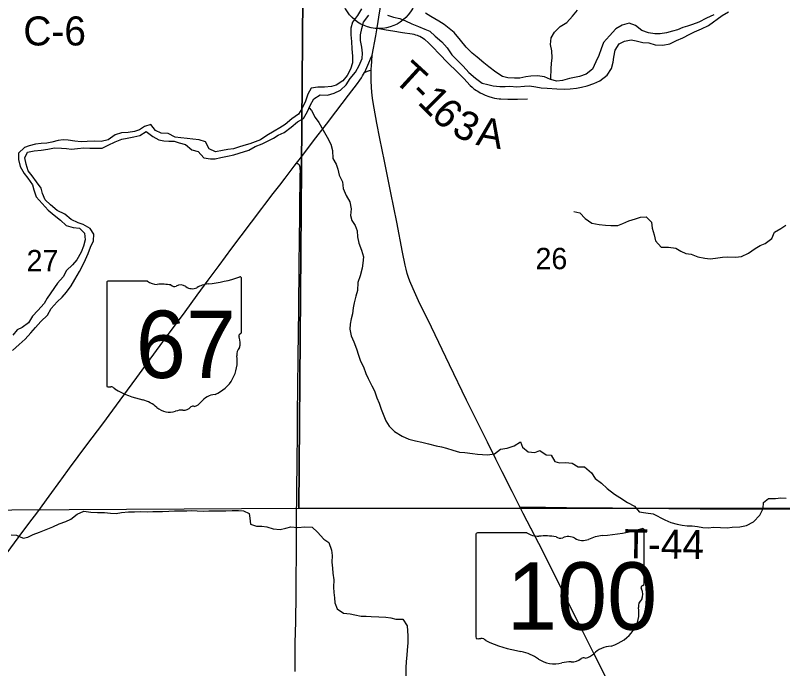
# Model space of a CAD drawing. Extents: x 0 to 34, y 0 to 22.
# Drawn here: x 7.184 to 7.934, y 14.745 to 15.384 of the extents above; entities that cross this region are included whole.
import ezdxf

# ---------------------------------------------------------------- set-up
doc = ezdxf.new("R2010")
doc.units = 0
for name, color, linetype in [('Default', 7, 'Continuous'), ('GM_X_County_Road_Text', 7, 'Continuous'), ('GM_X_Interchange_Ramps', 7, 'Continuous'), ('GM_X_Major_River', 7, 'Continuous'), ('GM_X_Minor_River', 7, 'Continuous'), ('GM_X_Section', 7, 'Continuous'), ('GM_X_Section_Text', 7, 'Continuous'), ('GM_X_State_Location', 7, 'Continuous'), ('GM_X_State_Route', 7, 'Continuous'), ('GM_X_State_Shield', 7, 'Continuous'), ('GM_X_Township_Road', 7, 'Continuous'), ('GM_X_Township_Road_Text', 7, 'Continuous'), ('GM_X_Unincorporated', 7, 'Continuous')]:
    doc.layers.add(name, color=color, linetype=linetype)

msp = doc.modelspace()

# ---------------------------------------------------------------- linework, layer by layer
at = {"layer": 'Default'}
msp.add_line((7.92809, 14.4004), (7.74937, 14.75957), dxfattribs=at)
msp.add_lwpolyline([(7.69144, 14.87495), (7.68009, 14.89684), (7.66922, 14.91837), (7.65961, 14.93739), (7.65347, 14.94996), (7.64531, 14.96644), (7.62464, 15.00761), (7.60807, 15.04207), (7.59039, 15.07893), (7.57789, 15.10487), (7.57257, 15.11647), (7.56943, 15.12394), (7.56809, 15.12753), (7.56675, 15.13163), (7.5656, 15.1359), (7.56475, 15.13978), (7.56219, 15.15228), (7.55651, 15.18158), (7.55066, 15.21052), (7.54457, 15.24131), (7.54011, 15.26356), (7.53717, 15.27851), (7.53444, 15.29318), (7.5332, 15.30086), (7.53257, 15.3058), (7.53188, 15.31325), (7.53147, 15.32072), (7.53139, 15.32726), (7.53146, 15.32971), (7.5316, 15.33201), (7.53172, 15.33398), (7.53253, 15.34511), (7.53597, 15.36398), (7.53727, 15.3717), (7.53827, 15.37764)], dxfattribs=at)
at = {"layer": 'GM_X_Interchange_Ramps'}
msp.add_lwpolyline([(7.53253, 15.34511), (7.53098, 15.34216), (7.52975, 15.33961), (7.52484, 15.3282)], dxfattribs=at)
at = {"layer": 'GM_X_Major_River'}
for points in [[(7.52199, 15.39029), (7.51798, 15.38386), (7.51321, 15.37743), (7.51167, 15.37155), (7.51145, 15.36491), (7.51218, 15.35864), (7.51253, 15.35124)], [(7.52314, 15.34702), (7.52241, 15.3531), (7.52092, 15.35956), (7.52113, 15.36506), (7.52229, 15.37132), (7.52403, 15.37738), (7.52918, 15.38419)], [(7.54759, 15.3843), (7.55328, 15.38238), (7.55953, 15.38084), (7.56503, 15.37873), (7.57128, 15.37585), (7.57791, 15.37317), (7.58397, 15.37067), (7.5889, 15.36857), (7.594, 15.3638), (7.60062, 15.35808), (7.60591, 15.35217), (7.61044, 15.34551), (7.61592, 15.33999), (7.6214, 15.33427), (7.62688, 15.32817), (7.63349, 15.32245), (7.64012, 15.31787), (7.64543, 15.31633), (7.65073, 15.31517), (7.65737, 15.31457), (7.6625, 15.31455), (7.66724, 15.31472), (7.67388, 15.31412), (7.68129, 15.31466), (7.68641, 15.31502), (7.69267, 15.31423), (7.6976, 15.31326), (7.70368, 15.31286), (7.71316, 15.31206), (7.72056, 15.31184), (7.72607, 15.31219), (7.73233, 15.31274), (7.73727, 15.31366), (7.74278, 15.31516), (7.74924, 15.31741), (7.75514, 15.32004), (7.76218, 15.3257), (7.76638, 15.33195), (7.76812, 15.3382), (7.7689, 15.34313), (7.77007, 15.34996), (7.77389, 15.35621), (7.77921, 15.35884), (7.78567, 15.35995), (7.7906, 15.35917), (7.79724, 15.35744), (7.80312, 15.35703), (7.80937, 15.3553), (7.81658, 15.35489), (7.82342, 15.35619), (7.83008, 15.35939), (7.83635, 15.36221), (7.84301, 15.36578), (7.84777, 15.36804), (7.85461, 15.37086), (7.86127, 15.37406), (7.87459, 15.38387), (7.88087, 15.38745)], [(7.86662, 15.38466), (7.8594, 15.38128), (7.85198, 15.37751), (7.84571, 15.37507), (7.84096, 15.37357), (7.8362, 15.37208), (7.83107, 15.37001), (7.82632, 15.36851), (7.82043, 15.36702), (7.81416, 15.36591), (7.80885, 15.36593), (7.80259, 15.3669), (7.79634, 15.3694), (7.7899, 15.37398), (7.78365, 15.37628), (7.777, 15.37441), (7.77091, 15.37083), (7.76443, 15.36403), (7.75871, 15.3576), (7.75641, 15.35135), (7.7541, 15.34491), (7.75123, 15.33846), (7.74778, 15.33146), (7.74169, 15.32636), (7.73523, 15.3243), (7.73048, 15.32337), (7.72554, 15.32225), (7.71851, 15.32038), (7.71319, 15.31965), (7.70694, 15.32138), (7.70087, 15.32388), (7.69405, 15.32504), (7.68759, 15.32469), (7.68284, 15.32376), (7.67677, 15.32265), (7.67164, 15.32248), (7.665, 15.32289), (7.66007, 15.32424), (7.65326, 15.32863), (7.64664, 15.33359), (7.64172, 15.3376), (7.63529, 15.34313), (7.63037, 15.34695), (7.62451, 15.35305), (7.61885, 15.3599), (7.6128, 15.36714), (7.60789, 15.37133), (7.60278, 15.37515), (7.59767, 15.3784), (7.58991, 15.38299), (7.58461, 15.38605)], [(7.18088, 15.05621), (7.18717, 15.06207), (7.19307, 15.06736), (7.19879, 15.07341), (7.20337, 15.07851), (7.20852, 15.08456), (7.21481, 15.09061), (7.21863, 15.09724), (7.22435, 15.10366), (7.2293, 15.1082), (7.23369, 15.11311), (7.23808, 15.11936), (7.24171, 15.1256), (7.24611, 15.13337), (7.24879, 15.13848), (7.25204, 15.14511), (7.25472, 15.15117), (7.25703, 15.15723), (7.2599, 15.16348), (7.26012, 15.16993), (7.25654, 15.17564), (7.24991, 15.17928), (7.24498, 15.181), (7.23816, 15.18445), (7.23192, 15.18941), (7.22454, 15.19324), (7.21791, 15.19858), (7.21262, 15.20372), (7.21018, 15.20981), (7.20868, 15.21513), (7.20434, 15.22103), (7.19981, 15.22712), (7.19604, 15.23188), (7.19398, 15.23853), (7.19287, 15.24461), (7.19536, 15.25029), (7.20181, 15.2514), (7.20865, 15.25232), (7.2153, 15.25324), (7.22194, 15.25435), (7.22858, 15.25414), (7.23352, 15.25393), (7.23845, 15.25315), (7.24414, 15.25369), (7.25041, 15.25442), (7.25629, 15.25421), (7.26256, 15.25399), (7.26825, 15.25397), (7.27414, 15.25698), (7.28099, 15.26018), (7.28765, 15.263), (7.29277, 15.26392), (7.29923, 15.26522), (7.30531, 15.26653), (7.3114, 15.27049), (7.31783, 15.26553), (7.3237, 15.26227), (7.32882, 15.2613), (7.33375, 15.26109), (7.33888, 15.26088), (7.34381, 15.25934), (7.35006, 15.2578), (7.35611, 15.25246), (7.36218, 15.25073), (7.36785, 15.24482), (7.3743, 15.24365), (7.37904, 15.24382), (7.38436, 15.24513), (7.39082, 15.24624), (7.39709, 15.24754), (7.40241, 15.24923), (7.41191, 15.25222), (7.418, 15.25561), (7.42484, 15.25843), (7.4296, 15.26069), (7.43587, 15.26389), (7.44063, 15.26671), (7.44633, 15.26935), (7.45338, 15.27482), (7.45928, 15.27973), (7.46518, 15.28331), (7.46919, 15.28994), (7.47188, 15.296), (7.47551, 15.30244), (7.4816, 15.30621), (7.48881, 15.30599), (7.49546, 15.30804), (7.50154, 15.31087), (7.50707, 15.31597), (7.51108, 15.3224), (7.51604, 15.32845), (7.51968, 15.33508), (7.52255, 15.34171), (7.52314, 15.34702)], [(7.51253, 15.35124), (7.51326, 15.34403), (7.51323, 15.33776), (7.51112, 15.33151), (7.50806, 15.32526), (7.50386, 15.32015), (7.49739, 15.31563), (7.49264, 15.31451), (7.48599, 15.31378), (7.47935, 15.31381), (7.4727, 15.31269), (7.46945, 15.30683), (7.46734, 15.30019), (7.4637, 15.29262), (7.46026, 15.28751), (7.45379, 15.28298), (7.44731, 15.27713), (7.44218, 15.27411), (7.43647, 15.27091), (7.42943, 15.26657), (7.42315, 15.26242), (7.41802, 15.26017), (7.41288, 15.25829), (7.40699, 15.2568), (7.40167, 15.25511), (7.39673, 15.25362), (7.39142, 15.25288), (7.3861, 15.25176), (7.37926, 15.25046), (7.3732, 15.25334), (7.36962, 15.26018), (7.36318, 15.2623), (7.35692, 15.26289), (7.35161, 15.26349), (7.34534, 15.26408), (7.33984, 15.26486), (7.33303, 15.2685), (7.3262, 15.26891), (7.32051, 15.2714), (7.31598, 15.2773), (7.30971, 15.27543), (7.30495, 15.27203), (7.30001, 15.27035), (7.29375, 15.26942), (7.28748, 15.26926), (7.28102, 15.2672), (7.27417, 15.26229), (7.26752, 15.26061), (7.26107, 15.26102), (7.25366, 15.26067), (7.24778, 15.26032), (7.24152, 15.26091), (7.23507, 15.26189), (7.23033, 15.26229), (7.22539, 15.26174), (7.21912, 15.26006), (7.21437, 15.25913), (7.20868, 15.25878), (7.20317, 15.25804), (7.19709, 15.25636), (7.19234, 15.25486), (7.18643, 15.24938), (7.1866, 15.24293), (7.18827, 15.23609), (7.19223, 15.22943), (7.19563, 15.22467), (7.20035, 15.21839), (7.20146, 15.21326), (7.2039, 15.20661), (7.20976, 15.19994), (7.21562, 15.19346), (7.22148, 15.1885), (7.22753, 15.18355), (7.2332, 15.1784), (7.24003, 15.17666), (7.2461, 15.17569), (7.2512, 15.17111), (7.25193, 15.16446), (7.2502, 15.15821), (7.2479, 15.15234), (7.2435, 15.14476), (7.2393, 15.13985), (7.23359, 15.13437), (7.23014, 15.12812), (7.22462, 15.12207), (7.21469, 15.10731), (7.21163, 15.1022), (7.20553, 15.09539), (7.20019, 15.08991), (7.19637, 15.0831), (7.19008, 15.07876), (7.18533, 15.0765), (7.18113, 15.0712)]]:
    msp.add_lwpolyline(points, dxfattribs=at)
at = {"layer": 'GM_X_Minor_River'}
for points in [[(7.7071, 15.32134), (7.70732, 15.32214), (7.70736, 15.3322), (7.70795, 15.33694), (7.70835, 15.34244), (7.70819, 15.34928), (7.70689, 15.35554), (7.70749, 15.36218), (7.71074, 15.36767), (7.71626, 15.37315), (7.72273, 15.37692), (7.72845, 15.38335), (7.73322, 15.38902)], [(7.47087, 15.29373), (7.47318, 15.29106), (7.47657, 15.28402), (7.48016, 15.27926), (7.48468, 15.27184), (7.48845, 15.26499), (7.49202, 15.25796), (7.49352, 15.25169), (7.49405, 15.24391), (7.49726, 15.23839), (7.49894, 15.23364), (7.50025, 15.22775), (7.50345, 15.22109), (7.50418, 15.21464), (7.507, 15.20779), (7.51077, 15.20171), (7.51188, 15.19487), (7.51128, 15.18823), (7.51259, 15.18329), (7.51579, 15.17853), (7.51786, 15.1734), (7.51821, 15.16751), (7.51933, 15.16106), (7.52215, 15.1544), (7.52383, 15.14794), (7.52342, 15.14168), (7.52264, 15.13656), (7.52071, 15.12917), (7.5186, 15.12254), (7.518, 15.11495), (7.51664, 15.10926), (7.51491, 15.10282), (7.51394, 15.09789), (7.51316, 15.0922), (7.512, 15.08727), (7.51102, 15.08196), (7.51062, 15.07703), (7.51193, 15.07038), (7.51456, 15.06467), (7.51719, 15.05783), (7.51906, 15.05156), (7.52093, 15.04586), (7.52395, 15.04034), (7.5262, 15.03369), (7.52864, 15.02875), (7.53203, 15.02152), (7.53485, 15.01676), (7.5371, 15.00992), (7.53936, 15.00479), (7.54123, 14.9989), (7.54574, 14.98749), (7.54894, 14.98217), (7.55443, 14.97702), (7.56181, 14.97243), (7.56844, 14.96956), (7.57488, 14.96763), (7.58114, 14.96647), (7.58759, 14.96473), (7.59517, 14.96299), (7.60029, 14.96202), (7.60503, 14.96067), (7.61147, 14.95856), (7.61792, 14.95682), (7.62304, 14.95623), (7.63044, 14.95525), (7.63556, 14.95466), (7.64049, 14.95445), (7.64524, 14.95424), (7.65226, 14.95516), (7.65798, 14.9595), (7.66443, 14.96061), (7.67127, 14.96305), (7.67755, 14.96682), (7.67962, 14.9615), (7.6851, 14.95692), (7.69155, 14.95651), (7.6965, 14.9582), (7.70274, 14.95419), (7.70748, 14.9536), (7.71107, 14.9477), (7.7158, 14.94616), (7.72169, 14.94671), (7.72814, 14.94592), (7.73401, 14.94229), (7.74027, 14.94245), (7.74689, 14.93654), (7.75047, 14.93083), (7.75671, 14.92644), (7.76239, 14.9213), (7.76938, 14.91576), (7.77468, 14.91232), (7.78207, 14.90736), (7.78888, 14.90391), (7.79361, 14.89839), (7.80005, 14.89722), (7.80726, 14.89624), (7.81862, 14.8905), (7.82469, 14.88782), (7.83075, 14.88628), (7.83568, 14.88531), (7.84042, 14.88472)], [(7.72974, 15.19224), (7.73543, 15.1907), (7.74091, 15.18536), (7.74715, 15.18059), (7.75436, 15.17942), (7.76081, 15.17882), (7.76574, 15.17842), (7.77257, 15.17858), (7.77771, 15.18027), (7.78341, 15.1829), (7.78987, 15.18496), (7.79481, 15.18646), (7.80032, 15.18682), (7.8058, 15.18186), (7.80635, 15.17597), (7.80821, 15.16933), (7.80971, 15.16344), (7.81519, 15.15734), (7.8224, 15.15712), (7.82942, 15.15614), (7.83434, 15.15346), (7.83926, 15.15116), (7.84439, 15.15038), (7.85102, 15.14789), (7.85784, 15.14634), (7.86315, 15.14575), (7.86828, 15.14649), (7.87512, 15.1476), (7.88043, 15.14776), (7.88764, 15.14754), (7.89372, 15.14809), (7.90038, 15.15129), (7.90704, 15.156), (7.91198, 15.15902), (7.91674, 15.16089), (7.9234, 15.1658), (7.92589, 15.17186), (7.93217, 15.17544), (7.93712, 15.17884)], [(7.84042, 14.88472), (7.84536, 14.8847), (7.85067, 14.88392), (7.85579, 14.88294), (7.86148, 14.88254), (7.86642, 14.88328), (7.87306, 14.88287), (7.87951, 14.88265), (7.88464, 14.88339), (7.89204, 14.88355), (7.8985, 14.88504), (7.90535, 14.88843), (7.91164, 14.89504), (7.9147, 14.90167), (7.9153, 14.90755), (7.92006, 14.91133), (7.92689, 14.91149), (7.9322, 14.91204), (7.93733, 14.91163)], [(7.17956, 14.87593), (7.18468, 14.87534), (7.19112, 14.87266), (7.19587, 14.87359), (7.20081, 14.87622), (7.20728, 14.87847), (7.2202, 14.88373), (7.22629, 14.88674), (7.23275, 14.8888), (7.2377, 14.89125), (7.24398, 14.89597), (7.25063, 14.89898), (7.25746, 14.898), (7.26372, 14.89778), (7.27074, 14.89756), (7.27644, 14.89716), (7.28194, 14.89676), (7.28745, 14.89768), (7.29409, 14.89822), (7.30016, 14.8982), (7.30624, 14.89855), (7.31269, 14.89834), (7.31782, 14.8985), (7.32256, 14.89867), (7.32749, 14.89865), (7.33357, 14.89882), (7.33907, 14.89917), (7.34553, 14.89915), (7.35122, 14.89931), (7.35616, 14.89967), (7.36147, 14.89946), (7.36754, 14.89886), (7.37286, 14.89922), (7.37779, 14.89939), (7.38937, 14.89934), (7.39544, 14.8995), (7.40189, 14.89967), (7.40664, 14.89927), (7.41213, 14.89678), (7.41268, 14.89203), (7.41342, 14.88633), (7.41948, 14.88441), (7.42441, 14.88439), (7.42935, 14.88361), (7.4356, 14.88169), (7.44243, 14.88109), (7.44813, 14.88239), (7.45307, 14.8837), (7.45971, 14.88291), (7.46673, 14.88364), (7.47375, 14.88342), (7.47905, 14.87828), (7.48528, 14.87161), (7.4902, 14.86836), (7.49283, 14.86076), (7.49319, 14.85544), (7.49297, 14.84899), (7.4937, 14.84311), (7.49387, 14.83836), (7.49498, 14.83171), (7.49457, 14.8245), (7.49493, 14.81938), (7.49548, 14.81425), (7.49603, 14.80932), (7.49828, 14.80342), (7.50453, 14.79903), (7.51079, 14.79844), (7.51553, 14.79747), (7.52179, 14.7963), (7.52653, 14.79609), (7.53146, 14.79607), (7.53905, 14.79547), (7.54569, 14.79525), (7.55081, 14.79447), (7.55574, 14.79331), (7.56258, 14.79347), (7.56653, 14.78681), (7.56725, 14.77694), (7.56722, 14.7703), (7.56663, 14.76309), (7.56641, 14.75797), (7.56563, 14.7519), (7.56541, 14.74564), (7.56537, 14.73501)]]:
    msp.add_lwpolyline(points, dxfattribs=at)
at = {"layer": 'GM_X_Section'}
for points in [[(7.46474, 15.40235), (7.46088, 14.90162), (6.9551, 14.89867), (6.9614, 15.40185)], [(7.46474, 15.40235), (7.95187, 15.40369), (7.95709, 14.90157), (7.46088, 14.90162)]]:
    msp.add_lwpolyline(points, close=True, dxfattribs=at)
at = {"layer": 'GM_X_State_Route'}
for points in [[(7.53151, 15.33054), (7.5316, 15.33201), (7.53172, 15.33398), (7.53253, 15.34511), (7.53597, 15.36398), (7.53727, 15.3717), (7.54007, 15.38837), (7.54304, 15.40596), (7.54651, 15.42748), (7.54903, 15.44292)], [(7.22903, 14.93074), (7.23662, 14.94107), (7.25346, 14.96379), (7.26892, 14.98443), (7.27887, 14.99795), (7.29321, 15.01749), (7.3022, 15.02979), (7.31523, 15.04759), (7.33147, 15.06959), (7.34948, 15.09415), (7.36128, 15.11015), (7.37221, 15.12488), (7.38291, 15.13939), (7.39523, 15.15616), (7.40439, 15.16832), (7.42453, 15.19516), (7.42754, 15.1991), (7.43572, 15.20966), (7.4422, 15.21801), (7.44749, 15.22492), (7.45634, 15.23654), (7.45856, 15.23941), (7.46463, 15.24723), (7.4752, 15.26115), (7.48781, 15.27765), (7.49707, 15.28976), (7.50936, 15.30584), (7.51821, 15.31742), (7.52054, 15.32055), (7.52203, 15.32298), (7.52311, 15.32492), (7.52391, 15.32648), (7.52484, 15.3282), (7.52619, 15.32881), (7.52709, 15.32919), (7.52792, 15.32951), (7.52884, 15.32981), (7.52991, 15.33013), (7.53151, 15.33054)], [(7.76748, 14.72338), (7.74937, 14.75957), (7.73847, 14.78123), (7.73042, 14.79718), (7.72079, 14.81656), (7.71031, 14.83772), (7.69537, 14.86736), (7.68793, 14.8817), (7.68009, 14.89684), (7.67694, 14.90308), (7.66922, 14.91837), (7.65961, 14.93739), (7.65347, 14.94996), (7.64531, 14.96644), (7.62464, 15.00761), (7.60807, 15.04207), (7.59039, 15.07893), (7.57789, 15.10487), (7.57257, 15.11647), (7.56943, 15.12394), (7.56809, 15.12753), (7.56675, 15.13163), (7.5656, 15.1359), (7.56475, 15.13978), (7.56219, 15.15228), (7.55651, 15.18158), (7.55066, 15.21052), (7.54457, 15.24131), (7.54011, 15.26356), (7.53717, 15.27851), (7.53444, 15.29318), (7.5332, 15.30086), (7.53257, 15.3058), (7.53188, 15.31325), (7.53147, 15.32072), (7.53139, 15.32726), (7.53146, 15.32971), (7.53151, 15.33054)], [(7.1755, 14.85835), (7.18631, 14.87277), (7.19664, 14.88677), (7.20541, 14.89845), (7.21666, 14.91371), (7.22797, 14.9293), (7.22903, 14.93074)]]:
    msp.add_lwpolyline(points, dxfattribs=at)
at = {"layer": 'GM_X_State_Shield'}
for p, q in [((7.27282, 15.12227), (7.27282, 15.02221)), ((7.31273, 15.12399), (7.27412, 15.12399)), ((7.40465, 15.07413), (7.40465, 15.12647)), ((7.40464, 15.07414), (7.40465, 15.07413)), ((7.63379, 14.87602), (7.63379, 14.77596)), ((7.68367, 14.87774), (7.63541, 14.87774)), ((7.79858, 14.82788), (7.79858, 14.88022)), ((7.79857, 14.82789), (7.79858, 14.82788))]:
    msp.add_line(p, q, dxfattribs=at)
for centre, radius, start, end in [((7.27433, 15.12248), 0.00153, 98.1301, 188.1301), ((7.32192, 15.1356), 0.01481, 231.61951, 271.11188), ((7.32683, 15.06781), 0.05318, 80.48669, 94.98827), ((7.37553, 15.09343), 0.02813, 97.34618, 120.76885), ((7.35769, 15.2604), 0.13981, 275.84447, 288.90645), ((7.40319, 15.12669), 0.00147, 351.86209, 97.738), ((7.33891, 15.123), 0.00427, 219.79206, 297.10237), ((7.34518, 15.11143), 0.00889, 54.46668, 119.14113), ((7.35665, 15.1273), 0.01069, 233.85621, 294.82819), ((7.40432, 15.07028), 0.00227, 107.94398, 210.33697), ((7.38987, 15.06367), 0.01363, 340.03296, 23.64957), ((7.40309, 15.07392), 0.00157, 289.60381, 7.73413), ((7.40991, 15.05222), 0.00992, 136.8065, 186.92959), ((7.36553, 15.04556), 0.03497, 292.30889, 8.98584), ((7.27434, 15.02199), 0.00154, 171.95839, 258.30661), ((7.27458, 15.03222), 0.01176, 267.33899, 280.60386), ((7.27698, 15.01643), 0.00424, 29.74838, 93.27175), ((7.33051, 15.10633), 0.10096, 240.41292, 257.1985), ((7.38027, 14.99412), 0.01915, 94.40312, 142.57675), ((7.30041, 14.97725), 0.03159, 47.18416, 75.83597), ((7.34763, 15.00844), 0.01068, 268.77702, 315.54927), ((7.35729, 14.99875), 0.00301, 65.75173, 132.64842), ((7.356, 15.01251), 0.0113, 282.87319, 323.27711), ((7.33458, 15.01594), 0.02004, 230.70037, 286.29184), ((7.34616, 14.98134), 0.01647, 85.69512, 111.20995)]:
    msp.add_arc(centre, radius, start, end, dxfattribs=at)
for centre, major_axis, start_param, end_param in [((7.73988, 15.01416), (0.17476, 0), 4.814394, 5.042369), ((7.79675, 14.88044), (0.00183, 0), 6.141152, 7.989035), ((7.63568, 14.87623), (0.00191, 0), 1.712693, 3.28349), ((7.69517, 14.88936), (0.01852, 0), 4.042523, 4.731795), ((7.70131, 14.82156), (0.06648, 0), 1.404758, 1.657858), ((7.7164, 14.87675), (0.00534, 0), 3.836095, 5.185415), ((7.72424, 14.86518), (0.01111, 0), 0.950623, 2.079405), ((7.76217, 14.84718), (0.03516, 0), 1.699011, 2.107814), ((7.73858, 14.88105), (0.01336, 0), 4.081561, 5.145723), ((7.79816, 14.82403), (0.00284, 0), 1.883978, 3.671073), ((7.7801, 14.81742), (0.01704, 0), 5.934695, 6.695948), ((7.79662, 14.82767), (0.00196, 0), 5.05454, 6.418171), ((7.80516, 14.80597), (0.0124, 0), 2.387724, 3.262537), ((7.74967, 14.79931), (0.04371, 0), 5.101752, 6.440018), ((7.6357, 14.77574), (0.00193, 0), 3.00124, 4.508301), ((7.63599, 14.78598), (0.0147, 0), 4.665946, 4.897461), ((7.63899, 14.77018), (0.0053, 0), 0.519207, 1.627899), ((7.70591, 14.86008), (0.1262, 0), 4.195997, 4.488961), ((7.66828, 14.731), (0.03949, 0), 0.823519, 1.323587), ((7.7681, 14.74787), (0.02394, 0), 1.647645, 2.488434), ((7.71099, 14.76969), (0.02506, 0), 4.026481, 4.996735), ((7.7273, 14.76219), (0.01335, 0), 4.691044, 5.507374), ((7.73937, 14.7525), (0.00376, 0), 1.147584, 2.315152), ((7.73777, 14.76626), (0.01412, 0), 4.937069, 5.64225), ((7.72547, 14.73509), (0.02059, 0), 1.495662, 1.94098)]:
    msp.add_ellipse(centre, major_axis=major_axis, ratio=0.8, start_param=start_param, end_param=end_param, dxfattribs=at)
at = {"layer": 'GM_X_Township_Road'}
for points in [[(7.53727, 15.3717), (7.53927, 15.37131), (7.54614, 15.36998), (7.55283, 15.36877), (7.56204, 15.36731), (7.57157, 15.36589), (7.57323, 15.3656), (7.57491, 15.36516), (7.57634, 15.36471), (7.57785, 15.36417), (7.57921, 15.36355), (7.58062, 15.36279), (7.58244, 15.36163), (7.58349, 15.36086), (7.58442, 15.36014), (7.58718, 15.35764), (7.59211, 15.35248), (7.59769, 15.34664), (7.60694, 15.3374), (7.61521, 15.32913), (7.62197, 15.32226), (7.62835, 15.31549), (7.63012, 15.31379), (7.63191, 15.31223), (7.63298, 15.31144), (7.63434, 15.31057), (7.63573, 15.30977), (7.63817, 15.30838), (7.64048, 15.30721), (7.64307, 15.30604), (7.64647, 15.30476), (7.64983, 15.30367), (7.6522, 15.30309), (7.65447, 15.30269), (7.65654, 15.30244), (7.65837, 15.30235), (7.66507, 15.30212), (7.67465, 15.30212), (7.6845, 15.30231)], [(7.45703, 14.74226), (7.45711, 14.74723), (7.45721, 14.75811), (7.45731, 14.76805), (7.45756, 14.78235), (7.45773, 14.78918), (7.45775, 14.79073), (7.45812, 14.81777), (7.45819, 14.82771), (7.45825, 14.83548), (7.45847, 14.85443), (7.45854, 14.85474), (7.45858, 14.85753), (7.45853, 14.86188), (7.45854, 14.86437), (7.45853, 14.87276), (7.45854, 14.87804), (7.4586, 14.8855), (7.45858, 14.89357), (7.45862, 14.89885), (7.45872, 14.90786), (7.45888, 14.92309), (7.45894, 14.92899), (7.45898, 14.93769), (7.45907, 14.95105), (7.45928, 14.97125), (7.45933, 14.97995), (7.45953, 14.99798), (7.45957, 15.00202), (7.45968, 15.01227), (7.45979, 15.01911), (7.45988, 15.02719), (7.46002, 15.04211), (7.46015, 15.05267), (7.46021, 15.05796), (7.46029, 15.0651), (7.46035, 15.07256), (7.46064, 15.0968), (7.46073, 15.10364), (7.46088, 15.11203), (7.46095, 15.12384), (7.46119, 15.14622), (7.46135, 15.15865), (7.4615, 15.17077), (7.46158, 15.18195), (7.46164, 15.19065), (7.46184, 15.2043), (7.46188, 15.20801), (7.46194, 15.21421), (7.46206, 15.22135), (7.46218, 15.22881), (7.46222, 15.23129), (7.4622, 15.23449), (7.46216, 15.23514), (7.46208, 15.23553), (7.46198, 15.23586), (7.46187, 15.23615), (7.46174, 15.23646), (7.46161, 15.23676), (7.46145, 15.23711), (7.46128, 15.23738), (7.46101, 15.23774), (7.46076, 15.23802), (7.46037, 15.23832), (7.4595, 15.23885), (7.45856, 15.23941)], [(7.67694, 14.90308), (7.68769, 14.90298), (7.70189, 14.90285), (7.72266, 14.9026), (7.75039, 14.90227), (7.76764, 14.9021), (7.78675, 14.90191), (7.8048, 14.90175), (7.82247, 14.90146), (7.83844, 14.90142), (7.85325, 14.90138), (7.88768, 14.90126), (7.9072, 14.90119), (7.91977, 14.90115), (7.93263, 14.90118), (7.95127, 14.9012)]]:
    msp.add_lwpolyline(points, dxfattribs=at)
at = {"layer": 'GM_X_Unincorporated'}
msp.add_circle((7.53908, 15.40829), 0.0372, dxfattribs=at)

# ---------------------------------------------------------------- texts
at = {"layer": 'GM_X_County_Road_Text'}
msp.add_text('C-6', height=0.028409, rotation=0.00001, dxfattribs=at).set_placement((7.19132, 15.35461))
at = {"layer": 'GM_X_Section_Text'}
for s, p in [('27', (7.19445, 15.13358)), ('26', (7.69215, 15.13567))]:
    msp.add_text(s, height=0.020928, rotation=0.00001, dxfattribs=at).set_placement(p)
at = {"layer": 'GM_X_State_Location'}
for s, p in [('s', (7.33725, 15.06558)), ('r', (7.33725, 15.06558)), ('s', (7.71433, 14.81934)), ('r', (7.71433, 14.81934))]:
    msp.add_text(s, height=0.0000947, dxfattribs=at).set_placement(p)
for s, p in [('67', (7.31341, 15.05869)), ('100', (7.6809, 14.81245))]:
    msp.add_text(s, height=0.0000947, rotation=0.00001, dxfattribs=at).set_placement(p)
at = {"layer": 'GM_X_State_Shield'}
for s, p in [('67', (7.30127, 15.02926)), ('100', (7.66415, 14.78301))]:
    msp.add_text(s, height=0.065918, dxfattribs=at).set_placement(p)
at = {"layer": 'GM_X_Township_Road_Text'}
for s, height, rotation, p in [('T', 0.02841, 317.54484, (7.55221, 15.32073)), ('-', 0.02841, 314.91997, (7.56764, 15.30662)), ('1', 0.02841, 315.00965, (7.57591, 15.29832)), ('6', 0.02841, 316.56119, (7.58889, 15.28537)), ('3', 0.02841, 333.38337, (7.60903, 15.26812)), ('A', 0.02841, 350.06435, (7.63322, 15.25746)), ('T-44', 0.028409, 359.29046, (7.77875, 14.853))]:
    msp.add_text(s, height=height, rotation=rotation, dxfattribs=at).set_placement(p)

doc.saveas('drawing.dxf')
